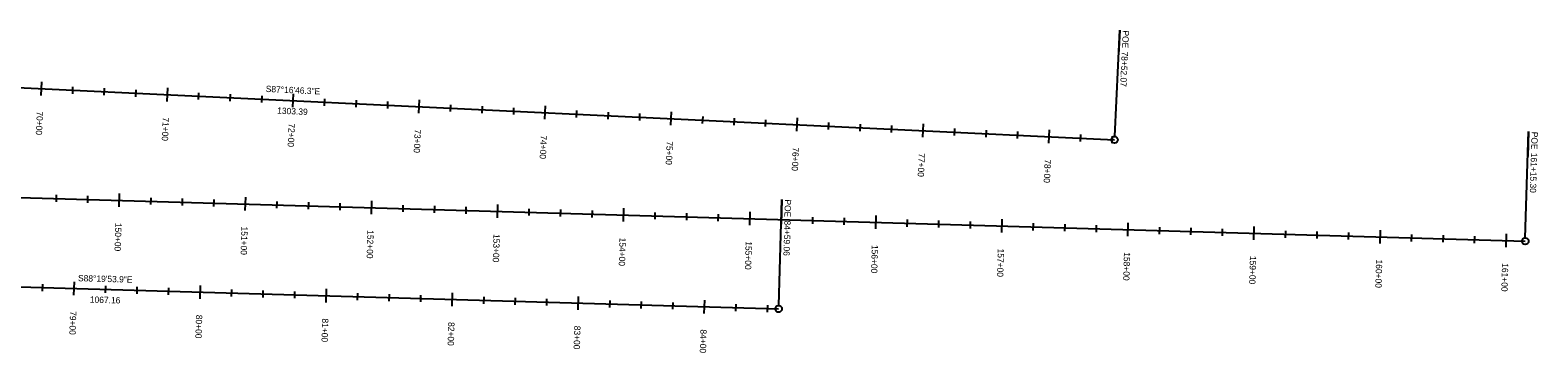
# Model space of a CAD drawing. Extents: x 2300830 to 2307917, y 756066 to 766359.
# Drawn here: x 2306721 to 2307917, y 760719 to 760975 of the extents above; entities that cross this region are included whole.
import ezdxf

# ---------------------------------------------------------------- set-up
doc = ezdxf.new("R2010")
doc.units = 0
for name, color, linetype in [('Default', 7, 'Continuous'), ('Draft_Bearing Label', 7, 'Continuous'), ('Draft_Station Cardinal Points', 7, 'Continuous'), ('Draft_Station Labels Major', 7, 'Continuous'), ('Draft_Station Ticks Major', 7, 'Continuous'), ('Draft_Station Ticks Minor', 7, 'Continuous'), ('Geom_Baseline', 7, 'Continuous')]:
    doc.layers.add(name, color=color, linetype=linetype)

msp = doc.modelspace()

# ---------------------------------------------------------------- linework, layer by layer
at = {"layer": 'Default'}
for p, q in [((2306279.1, 760949.8), (2307581, 760887.9)), ((2304792.6, 760898.1), (2307906.7, 760807.4)), ((2306248, 760784.7), (2307314.7, 760753.7))]:
    msp.add_line(p, q, dxfattribs=at)
at = {"layer": 'Draft_Station Cardinal Points'}
for p, q in [((2307581.2, 760890.6), (2307585.2, 760974.8)), ((2307585.2, 760974.8), (2307584.2, 760955.2)), ((2307581, 760887.9), (2307581, 760887.9)), ((2307906.7, 760810.1), (2307909.2, 760894.4)), ((2307909.2, 760894.4), (2307908.6, 760874.7)), ((2307314.8, 760756.3), (2307317.3, 760840.6)), ((2307317.3, 760840.6), (2307316.7, 760821)), ((2307906.7, 760807.4), (2307906.7, 760807.4)), ((2307314.7, 760753.7), (2307314.7, 760753.7))]:
    msp.add_line(p, q, dxfattribs=at)
for centre in [(2307581, 760887.9), (2307906.7, 760807.4), (2307314.7, 760753.7)]:
    msp.add_circle(centre, 2.67, dxfattribs=at)
at = {"layer": 'Draft_Station Ticks Major'}
for p, q in [((2306730.2, 760933.7), (2306729.7, 760923.1)), ((2306830.1, 760929), (2306829.6, 760918.3)), ((2306929.9, 760924.2), (2306929.4, 760913.6)), ((2307029.8, 760919.5), (2307029.3, 760908.9)), ((2307129.7, 760914.7), (2307129.2, 760904.1)), ((2307229.6, 760910), (2307229.1, 760899.4)), ((2307329.5, 760905.2), (2307329, 760894.6)), ((2307429.4, 760900.5), (2307428.9, 760889.9)), ((2307529.3, 760895.7), (2307528.8, 760885.1)), ((2306792, 760845.2), (2306791.7, 760834.6)), ((2306892, 760842.3), (2306891.6, 760831.7)), ((2306991.9, 760839.4), (2306991.6, 760828.8)), ((2307091.9, 760836.5), (2307091.6, 760825.9)), ((2307191.8, 760833.6), (2307191.5, 760823)), ((2307291.8, 760830.7), (2307291.5, 760820.1)), ((2307391.7, 760827.8), (2307391.4, 760817.2)), ((2307491.7, 760824.9), (2307491.4, 760814.2)), ((2307591.7, 760821.9), (2307591.3, 760811.3)), ((2307691.6, 760819), (2307691.3, 760808.4)), ((2307791.6, 760816.1), (2307791.3, 760805.5)), ((2307891.5, 760813.2), (2307891.2, 760802.6)), ((2306756.1, 760775.3), (2306755.8, 760764.7)), ((2306856, 760772.4), (2306855.7, 760761.8)), ((2306956, 760769.5), (2306955.7, 760758.8)), ((2307055.9, 760766.5), (2307055.6, 760755.9)), ((2307155.9, 760763.6), (2307155.6, 760753)), ((2307255.9, 760760.7), (2307255.5, 760750.1))]:
    msp.add_line(p, q, dxfattribs=at)
at = {"layer": 'Draft_Station Ticks Minor'}
for p, q in [((2306755, 760929.9), (2306754.8, 760924.4)), ((2306780, 760928.7), (2306779.7, 760923.2)), ((2306805, 760927.6), (2306804.7, 760922)), ((2306854.9, 760925.2), (2306854.6, 760919.7)), ((2306879.9, 760924), (2306879.6, 760918.5)), ((2306904.9, 760922.8), (2306904.6, 760917.3)), ((2306954.8, 760920.4), (2306954.5, 760914.9)), ((2306979.8, 760919.3), (2306979.5, 760913.7)), ((2307004.7, 760918.1), (2307004.5, 760912.6)), ((2307054.7, 760915.7), (2307054.4, 760910.2)), ((2307079.7, 760914.5), (2307079.4, 760909)), ((2307104.6, 760913.3), (2307104.4, 760907.8)), ((2307154.6, 760911), (2307154.3, 760905.4)), ((2307179.5, 760909.8), (2307179.3, 760904.3)), ((2307204.5, 760908.6), (2307204.3, 760903.1)), ((2307254.5, 760906.2), (2307254.2, 760900.7)), ((2307279.4, 760905), (2307279.2, 760899.5)), ((2307304.4, 760903.8), (2307304.1, 760898.3)), ((2307354.3, 760901.5), (2307354.1, 760895.9)), ((2307379.3, 760900.3), (2307379.1, 760894.8)), ((2307404.3, 760899.1), (2307404, 760893.6)), ((2307454.2, 760896.7), (2307454, 760891.2)), ((2307479.2, 760895.5), (2307478.9, 760890)), ((2307504.2, 760894.3), (2307503.9, 760888.8)), ((2307554.1, 760892), (2307553.9, 760886.5)), ((2307579.1, 760890.8), (2307578.8, 760885.3)), ((2306741.9, 760844.1), (2306741.8, 760838.6)), ((2306766.9, 760843.4), (2306766.8, 760837.9)), ((2306816.9, 760841.9), (2306816.7, 760836.4)), ((2306841.9, 760841.2), (2306841.7, 760835.7)), ((2306866.9, 760840.5), (2306866.7, 760835)), ((2306916.9, 760839), (2306916.7, 760833.5)), ((2306941.9, 760838.3), (2306941.7, 760832.8)), ((2306966.8, 760837.6), (2306966.7, 760832)), ((2307016.8, 760836.1), (2307016.7, 760830.6)), ((2307041.8, 760835.4), (2307041.7, 760829.9)), ((2307066.8, 760834.7), (2307066.6, 760829.1)), ((2307116.8, 760833.2), (2307116.6, 760827.7)), ((2307141.8, 760832.5), (2307141.6, 760827)), ((2307166.8, 760831.7), (2307166.6, 760826.2)), ((2307216.7, 760830.3), (2307216.6, 760824.8)), ((2307241.7, 760829.6), (2307241.6, 760824)), ((2307266.7, 760828.8), (2307266.6, 760823.3)), ((2307316.7, 760827.4), (2307316.5, 760821.9)), ((2307341.7, 760826.6), (2307341.5, 760821.1)), ((2307366.7, 760825.9), (2307366.5, 760820.4)), ((2307416.7, 760824.5), (2307416.5, 760818.9)), ((2307441.6, 760823.7), (2307441.5, 760818.2)), ((2307466.6, 760823), (2307466.5, 760817.5)), ((2307516.6, 760821.6), (2307516.4, 760816)), ((2307541.6, 760820.8), (2307541.4, 760815.3)), ((2307566.6, 760820.1), (2307566.4, 760814.6)), ((2307616.6, 760818.6), (2307616.4, 760813.1)), ((2307641.6, 760817.9), (2307641.4, 760812.4)), ((2307666.5, 760817.2), (2307666.4, 760811.7)), ((2307716.5, 760815.7), (2307716.4, 760810.2)), ((2307741.5, 760815), (2307741.4, 760809.5)), ((2307766.5, 760814.3), (2307766.3, 760808.8)), ((2307816.5, 760812.8), (2307816.3, 760807.3)), ((2307841.5, 760812.1), (2307841.3, 760806.6)), ((2307866.5, 760811.4), (2307866.3, 760805.8)), ((2306731, 760773.4), (2306730.8, 760767.9)), ((2306781, 760772), (2306780.8, 760766.5)), ((2306806, 760771.2), (2306805.8, 760765.7)), ((2306831, 760770.5), (2306830.8, 760765)), ((2306880.9, 760769.1), (2306880.8, 760763.5)), ((2306905.9, 760768.3), (2306905.8, 760762.8)), ((2306930.9, 760767.6), (2306930.8, 760762.1)), ((2306980.9, 760766.1), (2306980.7, 760760.6)), ((2307005.9, 760765.4), (2307005.7, 760759.9)), ((2307030.9, 760764.7), (2307030.7, 760759.2)), ((2307080.9, 760763.2), (2307080.7, 760757.7)), ((2307105.8, 760762.5), (2307105.7, 760757)), ((2307130.8, 760761.8), (2307130.7, 760756.3)), ((2307180.8, 760760.3), (2307180.7, 760754.8)), ((2307205.8, 760759.6), (2307205.6, 760754.1)), ((2307230.8, 760758.9), (2307230.6, 760753.4)), ((2307280.8, 760757.4), (2307280.6, 760751.9)), ((2307305.8, 760756.7), (2307305.6, 760751.2))]:
    msp.add_line(p, q, dxfattribs=at)
at = {"layer": 'Geom_Baseline'}
for p, q in [((2306279.1, 760949.8), (2307581, 760887.9)), ((2304792.6, 760898.1), (2307906.7, 760807.4)), ((2306248, 760784.7), (2307314.7, 760753.7))]:
    msp.add_line(p, q, dxfattribs=at)

# ---------------------------------------------------------------- texts
at = {"layer": 'Draft_Bearing Label'}
for s, rotation, p in [('S87°16\'46.3"E', 357.2795, (2306908, 760925.8)), ('1303.39', 357.2795, (2306917.1, 760908.6)), ('S88°19\'53.9"E', 358.3316, (2306759.2, 760775.7)), ('1067.16', 358.3316, (2306768.6, 760758.7))]:
    msp.add_text(s, height=5, rotation=rotation, dxfattribs=at).set_placement(p)
at = {"layer": 'Draft_Station Cardinal Points'}
for s, rotation, p in [('POE ', 267.2795, (2307587.6, 760974.7)), ('78+52.07', 267.2795, (2307586.8, 760958)), ('POE ', 268.3316, (2307911.7, 760894.3)), ('161+15.30', 268.3316, (2307911.2, 760877.6)), ('POE ', 268.3316, (2307319.7, 760840.6)), ('84+59.06', 268.3316, (2307319.3, 760823.9))]:
    msp.add_text(s, height=5, rotation=rotation, dxfattribs=at).set_placement(p)
at = {"layer": 'Draft_Station Labels Major'}
for s, rotation, p in [('70+00', 267.2795, (2306726.6, 760910.5)), ('71+00', 267.2795, (2306826.5, 760905.8)), ('72+00', 267.2795, (2306926.3, 760901)), ('73+00', 267.2795, (2307026.2, 760896.3)), ('74+00', 267.2795, (2307126.1, 760891.5)), ('75+00', 267.2795, (2307226, 760886.8)), ('76+00', 267.2795, (2307325.9, 760882)), ('77+00', 267.2795, (2307425.8, 760877.3)), ('78+00', 267.2795, (2307525.7, 760872.5)), ('150+00', 268.3316, (2306788.8, 760822)), ('151+00', 268.3316, (2306888.8, 760819.1)), ('152+00', 268.3316, (2306988.7, 760816.2)), ('153+00', 268.3316, (2307088.7, 760813.2)), ('154+00', 268.3316, (2307188.6, 760810.3)), ('155+00', 268.3316, (2307288.6, 760807.4)), ('156+00', 268.3316, (2307388.6, 760804.5)), ('157+00', 268.3316, (2307488.5, 760801.6)), ('158+00', 268.3316, (2307588.5, 760798.7)), ('159+00', 268.3316, (2307688.4, 760795.8)), ('160+00', 268.3316, (2307788.4, 760792.9)), ('161+00', 268.3316, (2307888.3, 760790)), ('79+00', 268.3316, (2306752.9, 760752)), ('80+00', 268.3316, (2306852.8, 760749.1)), ('81+00', 268.3316, (2306952.8, 760746.2)), ('82+00', 268.3316, (2307052.8, 760743.3)), ('83+00', 268.3316, (2307152.7, 760740.4)), ('84+00', 268.3316, (2307252.7, 760737.5))]:
    msp.add_text(s, height=5, rotation=rotation, dxfattribs=at).set_placement(p)

doc.saveas('drawing.dxf')
